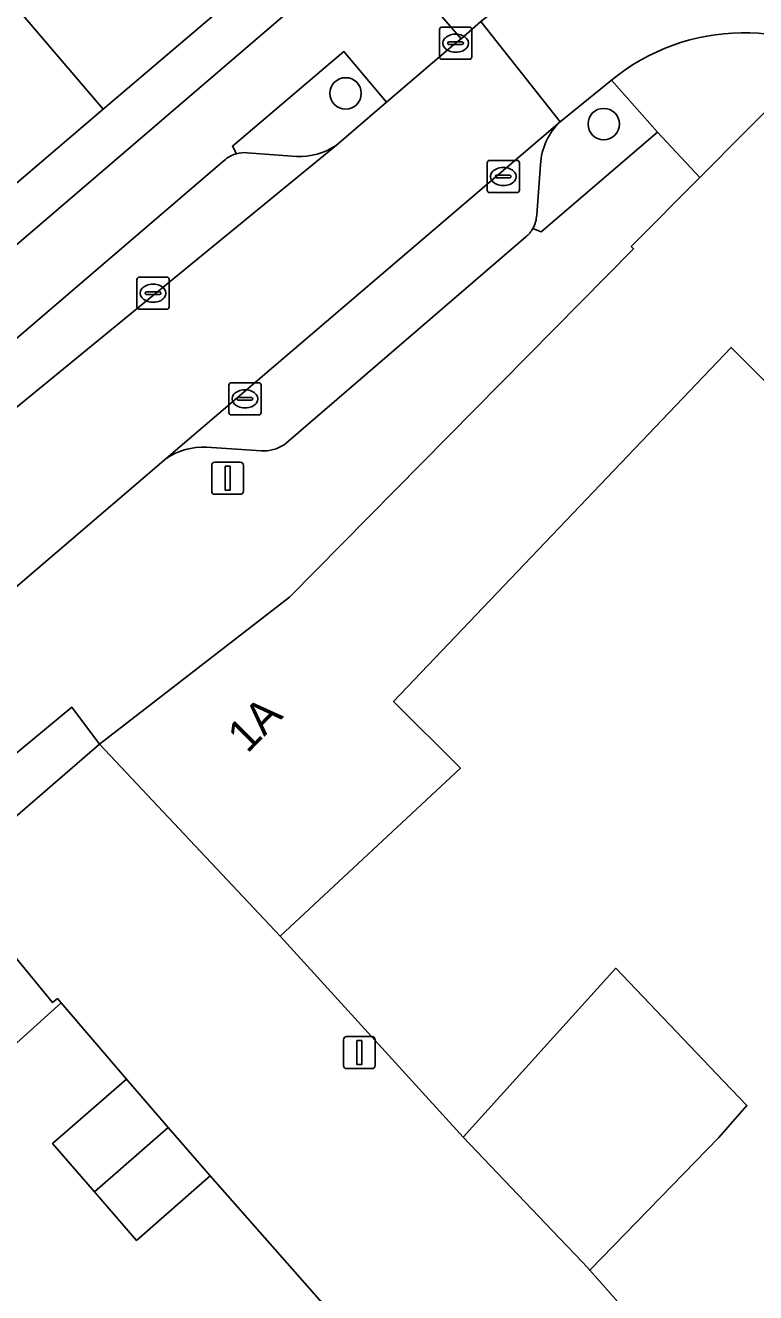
# Model space of a CAD drawing. Extents: x 160377 to 161131, y 383938 to 384853.
# Drawn here: x 160727.57 to 160750.28, y 384719.84 to 384759.23 of the extents above; entities that cross this region are included whole.
import ezdxf

# ---------------------------------------------------------------- set-up
doc = ezdxf.new("R2010")
doc.units = 0
for name, color, linetype in [('IMGEO_Boom', 7, 'Continuous'), ('IMGEO_Erf', 7, 'Continuous'), ('IMGEO_Groenvoorziening', 7, 'Continuous'), ('IMGEO_Kolk', 7, 'Continuous'), ('IMGEO_Lichtmast', 7, 'Continuous'), ('IMGEO_Pand', 7, 'Continuous'), ('IMGEO_Pand_nummerreeks', 7, 'Continuous'), ('IMGEO_Parkeervlak_open', 7, 'Continuous'), ('IMGEO_Rijbaan_lokaal_open', 7, 'Continuous'), ('IMGEO_Voetpad_open', 7, 'Continuous')]:
    doc.layers.add(name, color=color, linetype=linetype)

msp = doc.modelspace()

# ---------------------------------------------------------------- linework, layer by layer
at = {"layer": 'IMGEO_Boom'}
for centre in [(160737.528, 384757.116), (160745.559, 384756.161)]:
    msp.add_circle(centre, 0.489, dxfattribs=at)
at = {"layer": 'IMGEO_Erf'}
for points in [[(160734.334, 384760.327), (160729.987, 384756.626), (160725.646, 384752.931), (160721.098, 384749.06), (160722.045, 384747.922), (160736.526, 384760.339)], [(160750.859, 384747.879), (160749.519, 384749.219), (160739.021, 384738.216), (160741.098, 384736.14), (160735.496, 384730.919), (160741.188, 384724.668), (160745.936, 384729.923), (160749.285, 384726.415), (160750.013, 384725.653), (160749.143, 384724.657), (160745.125, 384720.534), (160749.596, 384715.479)], [(160709.239, 384719.292), (160719, 384727.623), (160719.042, 384727.659), (160725.936, 384733.492), (160729.878, 384736.884), (160729.01, 384738.039), (160724.996, 384734.726), (160721.238, 384731.526), (160717.571, 384728.403), (160713.903, 384725.28), (160710.143, 384722.078), (160708.357, 384720.551), (160707.54, 384719.853), (160738.184, 384683.931)], [(160737.415, 384718.828), (160733.318, 384723.469), (160731.028, 384721.462), (160729.72, 384722.967), (160728.412, 384724.471), (160730.709, 384726.469), (160728.683, 384728.844), (160722.93, 384723.667), (160726.209, 384719.818)]]:
    msp.add_lwpolyline(points, dxfattribs=at)
at = {"layer": 'IMGEO_Groenvoorziening'}
msp.add_lwpolyline([(160741.125, 384758.814), (160741.735, 384759.349), (160742.537, 384759.984), (160743.111, 384760.537), (160741.808, 384762.118), (160739.783, 384760.371)], close=True, dxfattribs=at)
for points in [[(160738.803, 384756.84), (160737.477, 384758.415), (160734.01, 384755.475), (160734.135, 384755.241)], [(160747.229, 384755.909), (160745.804, 384757.532), (160744.202, 384756.233)], [(160737.241, 384755.506), (160738.803, 384756.84)], [(160743.355, 384752.917), (160743.616, 384752.818), (160747.229, 384755.909)], [(160734.466, 384755.272), (160735.998, 384755.155)], [(160743.591, 384754.909), (160743.473, 384753.337)]]:
    msp.add_lwpolyline(points, dxfattribs=at)
for centre, radius, start, end in [((160745.579, 384754.795), 1.991, 133.7494, 176.7058), ((160736.082, 384757.234), 2.081, 267.6904, 303.847), ((160734.388, 384754.32), 0.955, 85.3272, 105.3737), ((160742.544, 384753.371), 0.929, 330.7326, 357.8818)]:
    msp.add_arc(centre, radius, start, end, dxfattribs=at)
at = {"layer": 'IMGEO_Kolk'}
for p, q in [((160740.451, 384758.25), (160740.451, 384759.102)), ((160740.526, 384759.176), (160741.378, 384759.176)), ((160741.452, 384759.102), (160741.452, 384758.25)), ((160740.71, 384758.67), (160740.71, 384758.682)), ((160741.148, 384758.633), (160740.75, 384758.633)), ((160740.753, 384758.719), (160741.151, 384758.719)), ((160740.939, 384758.956), (160740.964, 384758.956)), ((160741.194, 384758.682), (160741.194, 384758.67)), ((160740.962, 384758.396), (160740.937, 384758.396)), ((160741.378, 384758.176), (160740.526, 384758.176)), ((160742.009, 384755.032), (160742.861, 384755.032)), ((160741.934, 384754.106), (160741.934, 384754.958)), ((160742.422, 384754.812), (160742.447, 384754.812)), ((160742.935, 384754.958), (160742.935, 384754.106)), ((160742.193, 384754.526), (160742.193, 384754.538)), ((160742.631, 384754.489), (160742.233, 384754.489)), ((160742.236, 384754.575), (160742.634, 384754.575)), ((160742.445, 384754.252), (160742.42, 384754.252)), ((160742.677, 384754.538), (160742.677, 384754.526)), ((160742.861, 384754.032), (160742.009, 384754.032)), ((160731.039, 384750.479), (160731.039, 384751.331)), ((160731.114, 384751.405), (160731.966, 384751.405)), ((160731.527, 384751.185), (160731.552, 384751.185)), ((160732.04, 384751.331), (160732.04, 384750.479)), ((160731.298, 384750.899), (160731.298, 384750.911)), ((160731.736, 384750.862), (160731.338, 384750.862)), ((160731.341, 384750.948), (160731.739, 384750.948)), ((160731.782, 384750.911), (160731.782, 384750.899)), ((160731.966, 384750.405), (160731.114, 384750.405)), ((160731.55, 384750.625), (160731.525, 384750.625)), ((160733.898, 384747.195), (160733.898, 384748.047)), ((160733.973, 384748.121), (160734.825, 384748.121)), ((160734.899, 384748.047), (160734.899, 384747.195)), ((160734.157, 384747.615), (160734.157, 384747.627)), ((160734.595, 384747.578), (160734.197, 384747.578)), ((160734.2, 384747.664), (160734.598, 384747.664)), ((160734.386, 384747.901), (160734.411, 384747.901)), ((160734.641, 384747.627), (160734.641, 384747.615)), ((160734.409, 384747.341), (160734.384, 384747.341)), ((160734.825, 384747.121), (160733.973, 384747.121))]:
    msp.add_line(p, q, dxfattribs=at)
for points in [[(160740.451, 384758.25), (160740.451, 384759.102)], [(160740.526, 384759.176), (160741.378, 384759.176)], [(160741.452, 384759.102), (160741.452, 384758.25)], [(160741.378, 384758.176), (160740.526, 384758.176)], [(160742.009, 384755.032), (160742.861, 384755.032)], [(160741.934, 384754.106), (160741.934, 384754.958)], [(160742.935, 384754.958), (160742.935, 384754.106)], [(160742.861, 384754.032), (160742.009, 384754.032)], [(160731.039, 384750.479), (160731.039, 384751.331)], [(160731.114, 384751.405), (160731.966, 384751.405)], [(160732.04, 384751.331), (160732.04, 384750.479)], [(160731.966, 384750.405), (160731.114, 384750.405)], [(160733.898, 384747.195), (160733.898, 384748.047)], [(160733.973, 384748.121), (160734.825, 384748.121)], [(160734.899, 384748.047), (160734.899, 384747.195)], [(160734.825, 384747.121), (160733.973, 384747.121)]]:
    msp.add_lwpolyline(points, dxfattribs=at)
for centre, radius, start, end in [((160740.528, 384759.1), 0.0765, 91.552, 178.448), ((160740.528, 384759.1), 0.0765, 91.552, 178.448), ((160741.376, 384759.1), 0.0765, 1.552, 88.448), ((160741.376, 384759.1), 0.0765, 1.552, 88.448), ((160740.75, 384758.679), 0.0403, 85.8775, 175.7526), ((160740.747, 384758.669), 0.0366, 178.938, 274.7102), ((160741.151, 384758.676), 0.043, 264.8664, 352.4533), ((160741.155, 384758.681), 0.0386, 1.7309, 96.639), ((160740.528, 384758.252), 0.0765, 181.552, 268.448), ((160740.528, 384758.252), 0.0765, 181.552, 268.448), ((160741.376, 384758.252), 0.0765, 271.552, 358.448), ((160741.376, 384758.252), 0.0765, 271.552, 358.448), ((160742.011, 384754.956), 0.0765, 91.552, 178.448), ((160742.011, 384754.956), 0.0765, 91.552, 178.448), ((160742.859, 384754.956), 0.0765, 1.552, 88.448), ((160742.859, 384754.956), 0.0765, 1.552, 88.448), ((160742.233, 384754.535), 0.0403, 85.8775, 175.7526), ((160742.23, 384754.525), 0.0366, 178.938, 274.7102), ((160742.634, 384754.532), 0.043, 264.8664, 352.4533), ((160742.638, 384754.537), 0.0386, 1.7309, 96.639), ((160742.011, 384754.108), 0.0765, 181.552, 268.448), ((160742.011, 384754.108), 0.0765, 181.552, 268.448), ((160742.859, 384754.108), 0.0765, 271.552, 358.448), ((160742.859, 384754.108), 0.0765, 271.552, 358.448), ((160731.116, 384751.329), 0.0765, 91.552, 178.448), ((160731.116, 384751.329), 0.0765, 91.552, 178.448), ((160731.964, 384751.329), 0.0765, 1.552, 88.448), ((160731.964, 384751.329), 0.0765, 1.552, 88.448), ((160731.338, 384750.908), 0.0403, 85.8775, 175.7526), ((160731.335, 384750.898), 0.0366, 178.938, 274.7102), ((160731.739, 384750.905), 0.043, 264.8664, 352.4533), ((160731.743, 384750.91), 0.0386, 1.7309, 96.639), ((160731.116, 384750.481), 0.0765, 181.552, 268.448), ((160731.116, 384750.481), 0.0765, 181.552, 268.448), ((160731.964, 384750.481), 0.0765, 271.552, 358.448), ((160731.964, 384750.481), 0.0765, 271.552, 358.448), ((160733.975, 384748.045), 0.0765, 91.552, 178.448), ((160733.975, 384748.045), 0.0765, 91.552, 178.448), ((160734.823, 384748.045), 0.0765, 1.552, 88.448), ((160734.823, 384748.045), 0.0765, 1.552, 88.448), ((160734.197, 384747.624), 0.0403, 85.8775, 175.7526), ((160734.194, 384747.614), 0.0366, 178.938, 274.7102), ((160734.598, 384747.621), 0.043, 264.8664, 352.4533), ((160734.602, 384747.626), 0.0386, 1.7309, 96.639), ((160733.975, 384747.197), 0.0765, 181.552, 268.448), ((160733.975, 384747.197), 0.0765, 181.552, 268.448), ((160734.823, 384747.197), 0.0765, 271.552, 358.448), ((160734.823, 384747.197), 0.0765, 271.552, 358.448)]:
    msp.add_arc(centre, radius, start, end, dxfattribs=at)
for centre, major_axis, ratio, start_param, end_param in [((160740.938, 384758.676), (-0.387, 0.002), 0.722429, 4.712389, 7.853982), ((160740.963, 384758.676), (-0.39, 0.002), 0.717154, 1.570796, 4.712389), ((160742.421, 384754.532), (-0.387, 0.002), 0.722429, 4.712389, 7.853982), ((160742.446, 384754.532), (-0.39, 0.002), 0.717154, 1.570796, 4.712389), ((160731.526, 384750.905), (-0.387, 0.002), 0.722429, 4.712389, 7.853982), ((160731.551, 384750.905), (-0.39, 0.002), 0.717154, 1.570796, 4.712389), ((160734.385, 384747.621), (-0.387, 0.002), 0.722429, 4.712389, 7.853982), ((160734.41, 384747.621), (-0.39, 0.002), 0.717154, 1.570796, 4.712389)]:
    msp.add_ellipse(centre, major_axis=major_axis, ratio=ratio, start_param=start_param, end_param=end_param, dxfattribs=at)
at = {"layer": 'IMGEO_Lichtmast'}
for p, q in [((160733.463, 384745.654), (160734.253, 384745.654)), ((160734.253, 384745.654), (160733.463, 384745.654)), ((160733.363, 384744.754), (160733.363, 384745.554)), ((160733.363, 384745.554), (160733.363, 384744.754)), ((160734.353, 384745.554), (160734.353, 384744.754)), ((160734.353, 384744.754), (160734.353, 384745.554)), ((160734.253, 384744.654), (160733.463, 384744.654)), ((160733.463, 384744.654), (160734.253, 384744.654)), ((160737.461, 384726.9), (160737.461, 384727.7)), ((160737.461, 384727.7), (160737.461, 384726.9)), ((160737.561, 384727.8), (160738.351, 384727.8)), ((160738.351, 384727.8), (160737.561, 384727.8)), ((160738.451, 384727.7), (160738.451, 384726.9)), ((160738.451, 384726.9), (160738.451, 384727.7)), ((160738.351, 384726.8), (160737.561, 384726.8)), ((160737.561, 384726.8), (160738.351, 384726.8))]:
    msp.add_line(p, q, dxfattribs=at)
for points in [[(160733.783, 384745.529), (160733.933, 384745.529), (160733.933, 384744.779), (160733.783, 384744.779), (160733.783, 384745.529)], [(160737.881, 384727.675), (160738.031, 384727.675), (160738.031, 384726.925), (160737.881, 384726.925), (160737.881, 384727.675)]]:
    msp.add_lwpolyline(points, dxfattribs=at)
for centre, start, end in [((160733.463, 384745.554), 90, 180), ((160733.463, 384745.554), 90, 180), ((160734.253, 384745.554), 0, 90), ((160734.253, 384745.554), 360, 90), ((160733.463, 384744.754), 180, 270), ((160733.463, 384744.754), 180, 270), ((160734.253, 384744.754), 270, 0), ((160734.253, 384744.754), 270, 0), ((160737.561, 384727.7), 90, 180), ((160737.561, 384727.7), 90, 180), ((160738.351, 384727.7), 0, 90), ((160738.351, 384727.7), 360, 90), ((160737.561, 384726.9), 180, 270), ((160737.561, 384726.9), 180, 270), ((160738.351, 384726.9), 270, 0), ((160738.351, 384726.9), 270, 0)]:
    msp.add_arc(centre, 0.1, start, end, dxfattribs=at)
at = {"layer": 'IMGEO_Pand'}
for points in [[(160726.563, 384769.418), (160724.722, 384771.581), (160720.374, 384767.879), (160721.437, 384766.631), (160722.118, 384765.831), (160729.987, 384756.626), (160734.334, 384760.327)], [(160717.093, 384762.933), (160725.646, 384752.931), (160729.987, 384756.626), (160722.118, 384765.831), (160721.437, 384766.631)], [(160759.95, 384748.985), (160759.765, 384749.167), (160755.905, 384752.962), (160751.412, 384757.38), (160748.551, 384754.502), (160746.415, 384752.353), (160746.486, 384752.283), (160735.779, 384741.456), (160729.878, 384736.884), (160735.496, 384730.919), (160741.098, 384736.14), (160739.021, 384738.216), (160749.519, 384749.219), (160750.859, 384747.879), (160753.908, 384744.853), (160754.997, 384743.772), (160756.473, 384745.259)], [(160728.683, 384728.844), (160728.567, 384728.98), (160728.415, 384728.855), (160726.419, 384731.274), (160727.221, 384731.935), (160725.936, 384733.492), (160719.042, 384727.659), (160719, 384727.623), (160722.654, 384723.419), (160722.93, 384723.667)], [(160750.013, 384725.653), (160749.285, 384726.415), (160745.936, 384729.923), (160741.188, 384724.668), (160744.176, 384721.538), (160744.904, 384720.775), (160745.125, 384720.534), (160749.143, 384724.657)], [(160732.008, 384724.976), (160730.709, 384726.469), (160728.412, 384724.471), (160729.72, 384722.967)], [(160732.008, 384724.976), (160729.72, 384722.967), (160731.028, 384721.462), (160733.318, 384723.469)]]:
    msp.add_lwpolyline(points, close=True, dxfattribs=at)
at = {"layer": 'IMGEO_Parkeervlak_open'}
for points in [[(160744.202, 384756.233), (160731.944, 384745.767)], [(160733.752, 384755.029), (160724.607, 384747.204), (160725.648, 384746.015), (160737.241, 384755.506)], [(160735.998, 384755.155), (160734.466, 384755.272)], [(160743.473, 384753.337), (160743.591, 384754.909)], [(160735.618, 384746.195), (160743.136, 384752.656)], [(160733.204, 384746.121), (160734.916, 384746.002)]]:
    msp.add_lwpolyline(points, dxfattribs=at)
for centre, radius, start, end in [((160745.579, 384754.795), 1.991, 133.7494, 176.7058), ((160736.082, 384757.234), 2.081, 267.6904, 303.847), ((160734.38, 384754.346), 0.928, 105.326, 132.6052), ((160734.388, 384754.32), 0.955, 85.3272, 105.3737), ((160742.544, 384753.371), 0.929, 330.7326, 357.8818), ((160742.571, 384753.353), 0.897, 309.0529, 330.9484), ((160733.118, 384744.008), 2.115, 87.6695, 123.7161), ((160734.957, 384747.227), 1.226, 268.1012, 302.6437)]:
    msp.add_arc(centre, radius, start, end, dxfattribs=at)
at = {"layer": 'IMGEO_Rijbaan_lokaal_open'}
for points in [[(160743.111, 384760.537), (160742.537, 384759.984), (160741.735, 384759.349), (160744.202, 384756.233), (160745.804, 384757.532)], [(160731.944, 384745.767), (160744.202, 384756.233), (160741.735, 384759.349), (160741.125, 384758.814), (160740.952, 384758.676), (160738.803, 384756.84), (160737.241, 384755.506), (160725.648, 384746.015), (160724.5, 384745.075), (160718.994, 384740.2), (160715.7, 384737.108), (160705.726, 384728.632), (160705, 384727.959), (160707.541, 384724.965), (160708.342, 384725.62)], [(160716.265, 384732.379), (160718.829, 384734.562), (160720.28, 384735.803), (160721.762, 384737.062), (160731.944, 384745.767)], [(160749.596, 384715.479), (160745.125, 384720.534), (160744.904, 384720.775), (160744.176, 384721.538), (160741.188, 384724.668), (160735.496, 384730.919), (160729.878, 384736.884), (160725.936, 384733.492), (160727.221, 384731.935), (160726.419, 384731.274), (160728.415, 384728.855), (160728.567, 384728.98), (160728.683, 384728.844), (160730.709, 384726.469), (160732.008, 384724.976), (160733.318, 384723.469), (160737.415, 384718.828)]]:
    msp.add_lwpolyline(points, dxfattribs=at)
msp.add_arc((160749.923, 384752.489), 6.511, 52.3487, 129.2365, dxfattribs=at)
at = {"layer": 'IMGEO_Voetpad_open'}
for points in [[(160734.135, 384755.241), (160734.01, 384755.475), (160737.477, 384758.415), (160738.803, 384756.84), (160740.952, 384758.676), (160741.125, 384758.814), (160739.783, 384760.371), (160741.808, 384762.118), (160740.025, 384763.323), (160736.526, 384760.339), (160722.045, 384747.922), (160722.043, 384747.92), (160721.911, 384748.033), (160720.614, 384746.931), (160699.643, 384729.116), (160703.226, 384726.576), (160704.18, 384727.293), (160702.821, 384728.902), (160706.263, 384731.825), (160706.511, 384731.695)], [(160745.804, 384757.532), (160747.229, 384755.909), (160748.551, 384754.502), (160751.412, 384757.38), (160755.905, 384752.962), (160759.765, 384749.167), (160760.496, 384750), (160761.494, 384751.138), (160756.346, 384755.582), (160755.096, 384756.649), (160754.127, 384757.464), (160753.9, 384757.644)], [(160735.779, 384741.456), (160746.486, 384752.283), (160746.415, 384752.353), (160748.551, 384754.502), (160747.229, 384755.909), (160743.616, 384752.818), (160743.355, 384752.917)], [(160723.485, 384746.244), (160724.607, 384747.204), (160733.752, 384755.029)], [(160743.136, 384752.656), (160735.618, 384746.195)], [(160734.916, 384746.002), (160733.204, 384746.121)], [(160731.944, 384745.767), (160721.762, 384737.062), (160720.28, 384735.803), (160718.829, 384734.562), (160720.244, 384732.893), (160715.672, 384728.976), (160715.398, 384729.111)], [(160705.415, 384722.095), (160707.54, 384719.853), (160708.357, 384720.551), (160710.143, 384722.078), (160713.903, 384725.28), (160717.571, 384728.403), (160721.238, 384731.526), (160724.996, 384734.726), (160729.01, 384738.039), (160729.878, 384736.884), (160735.779, 384741.456)]]:
    msp.add_lwpolyline(points, dxfattribs=at)
for centre, radius, start, end in [((160749.923, 384752.489), 6.511, 52.3487, 129.2365), ((160734.38, 384754.346), 0.928, 105.326, 132.6052), ((160742.571, 384753.353), 0.897, 309.0529, 330.9484), ((160733.118, 384744.008), 2.115, 87.6695, 123.7161), ((160734.957, 384747.227), 1.226, 268.1012, 302.6437)]:
    msp.add_arc(centre, radius, start, end, dxfattribs=at)

# ---------------------------------------------------------------- texts
at = {"layer": 'IMGEO_Pand_nummerreeks'}
msp.add_text('1A', height=1, rotation=45.321, dxfattribs=at).set_placement((160734.473, 384736.58))

doc.saveas('drawing.dxf')
